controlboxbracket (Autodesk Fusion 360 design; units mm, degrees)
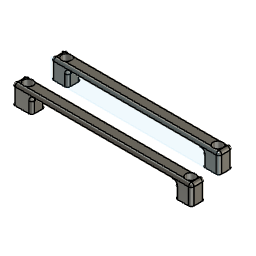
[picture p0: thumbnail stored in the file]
box_primitive "BoxPrimitive1" DistanceX 5 DistanceY 65 DistanceZ 7 OffsetDistanceX 0 OffsetDistanceY 0
hole "Hole1" HoleDepth 7 HoleDiameter 3.5 TipAngle 180
rectangular_pattern "R-Pattern1" uSpaceDistance 59 vSpaceDistance 0
sketch "Sketch3" plane through (0, -5, 0) normal (0, -1, 0) x axis (1, 0, 0)
  line L1 (0, 0) -> (0, 7)
  line L2 (65, 0) -> (0, 0)
  line L3 (65, 7) -> (65, 0)
  line L4 (0, 7) -> (65, 7)
  line L5 (59, 0) -> (7, 0)
  line L6 (59, 5) -> (59, 0)
  line L7 (7, 5) -> (59, 5)
  line L8 (7, 0) -> (7, 5)
  point P6 (7, 0)
  horizontal L5
  vertical L6
  horizontal L7
  vertical L8
  coincident L2 P6
extrude "Extrude1" cut sketch "Sketch3" profile of L2 L5 L6 L7 L8 against normal blind 11
fillet "Fillet1" radius 1 1 1
sketch "Sketch4" plane through (0, 0, 0) normal (0, 0, 1) x axis (1, 0, 0)
box_primitive "BoxPrimitive2" DistanceX 5 DistanceY 61 DistanceZ 7 OffsetDistanceX 0 OffsetDistanceY 0
hole "Hole2" HoleDepth 8 HoleDiameter 3.5 TipAngle 180
rectangular_pattern "R-Pattern2" uSpaceDistance 55 vSpaceDistance 0
sketch "Sketch7" plane through (0, 10, 0) normal (0, -1, 0) x axis (1, 0, 0)
  line L1 (-1, 0) -> (-1, 7)
  line L2 (60, 0) -> (-1, 0)
  line L3 (60, 7) -> (60, 0)
  line L4 (-1, 7) -> (60, 7)
sketch "Sketch8" plane through (0, 15, 0) normal (0, 1, 0) x axis (-1, 0, 0)
  line L1 (-60, 0) -> (-60, 7)
  line L2 (1, 0) -> (-60, 0)
  line L3 (1, 7) -> (1, 0)
  line L4 (-60, 7) -> (1, 7)
  line L5 (-5, 5) -> (-54, 5)
  line L6 (-5, 0) -> (-5, 5)
  line L7 (-54, 0) -> (-5, 0)
  line L8 (-54, 5) -> (-54, 0)
  point P8 (-5, 0)
  horizontal L5
  vertical L6
  horizontal L7
  vertical L8
  coincident L2 P8
extrude "Extrude2" cut sketch "Sketch8" profile of L2 L5 L6 L7 L8 against normal blind 8.5
fillet "Fillet2" radius 1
